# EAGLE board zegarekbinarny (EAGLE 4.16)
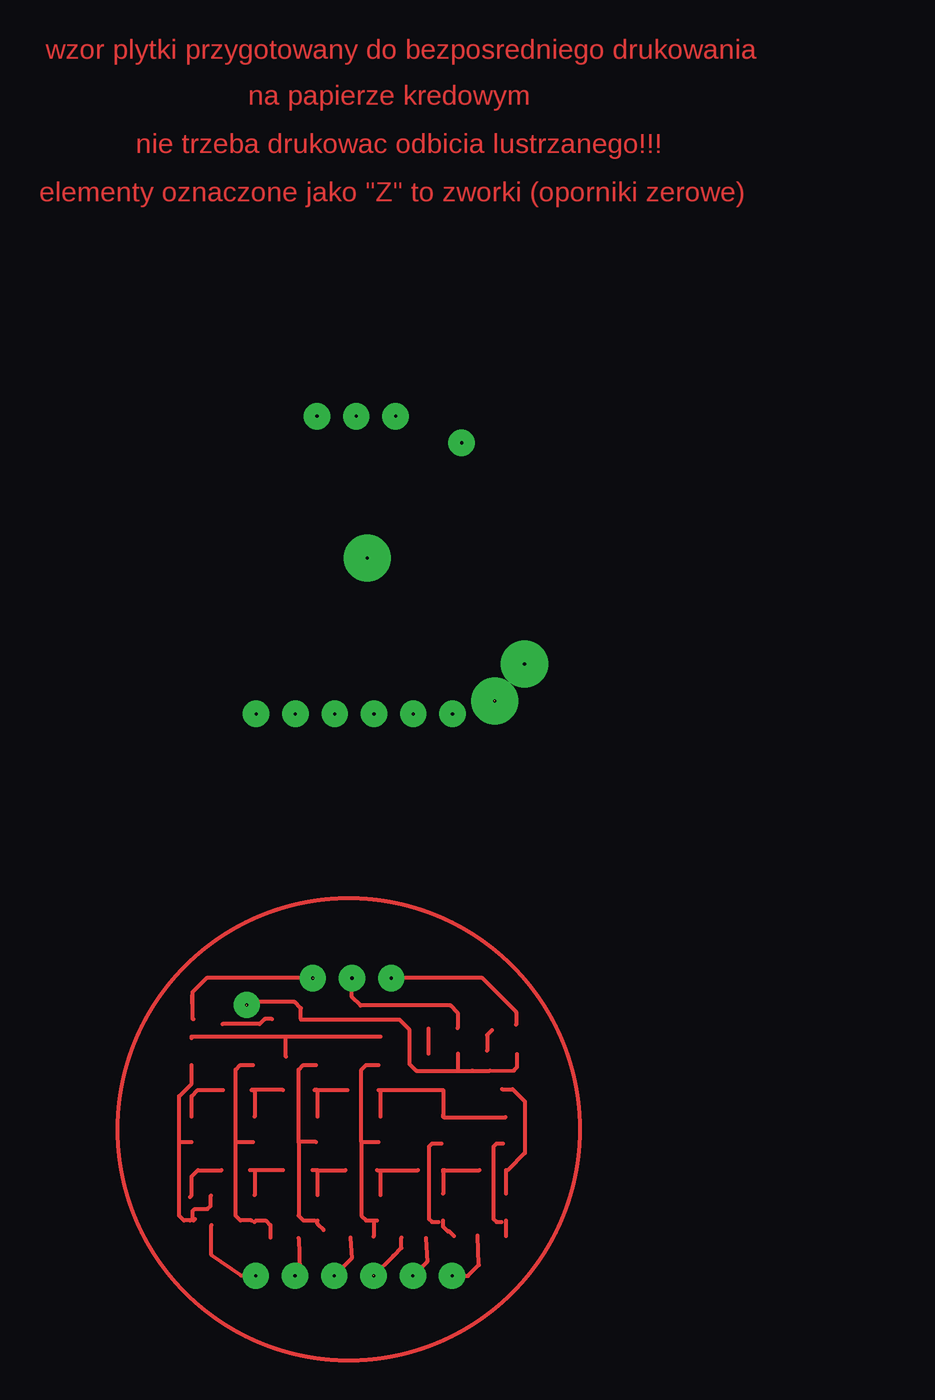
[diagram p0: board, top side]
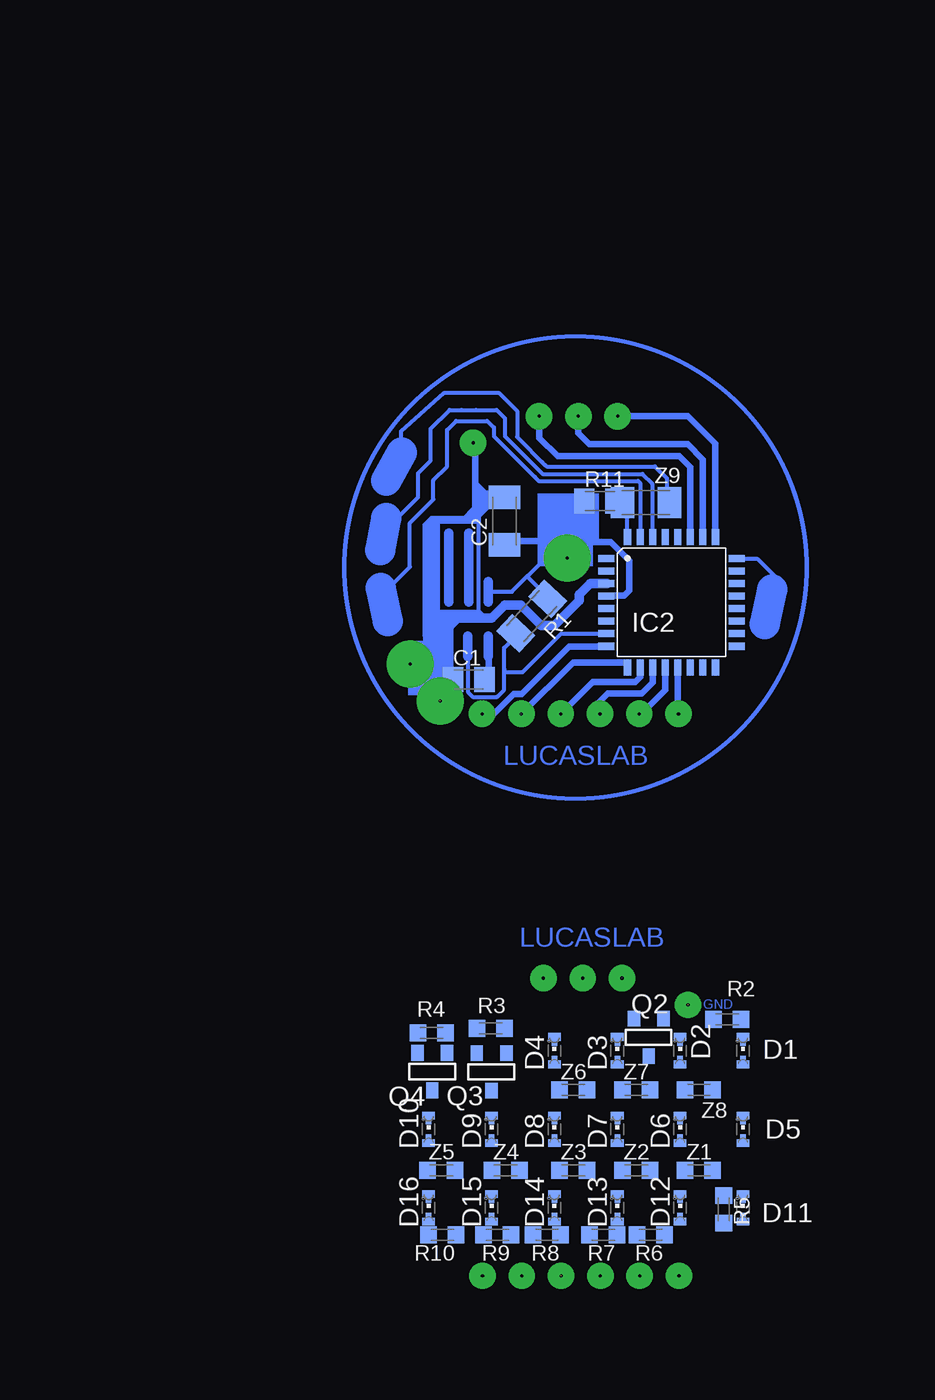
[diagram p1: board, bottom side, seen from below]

No outline drawn. Coordinates in mm, seen from the top.
Copper layers (1*16): Top 0.035mm / dielectric 1.5mm / Bottom 0.035mm
Design rules "default": minimum track width 10mil, minimum drill 24mil, track to track 8mil, track to pad 8mil, pad to pad 8mil, via to via 8mil, smd to smd 8mil, copper to edge 40mil, drill to drill 8mil, minimum pad ring 10mil, minimum via ring 8mil, stop-mask expansion 4mil, vias tented up to drill 0mil, thermal gap 10mil

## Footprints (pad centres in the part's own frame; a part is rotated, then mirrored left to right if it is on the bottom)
C0805K = smd 1.3 x 1.6: 1 -1,0; 2 1,0
C1206K = smd 1.5 x 2: 1 -1.5,0; 2 1.5,0
CHIPLED-0603-TTW = smd 0.8 x 0.5: A 0,-0.875; C 0,0.875 | smd 0.35 x 0.35: A@1 0,-0.5; C@1 0,0.5
VQFP32 = smd 1 x 0.45: 1 -4.15,2.8; 2 -4.15,2; 3 -4.15,1.2; 4 -4.15,0.4; 5 -4.15,-0.4; 6 -4.15,-1.2; 7 -4.15,-2; 8 -4.15,-2.8; 17 4.15,-2.8; 18 4.15,-2; 19 4.15,-1.2; 20 4.15,-0.4; 21 4.15,0.4; 22 4.15,1.2; 23 4.15,2; 24 4.15,2.8 | smd 0.45 x 1: 9 -2.8,-4.15; 10 -2,-4.15; 11 -1.2,-4.15; 12 -0.4,-4.15; 13 0.4,-4.15; 14 1.2,-4.15; 15 2,-4.15; 16 2.8,-4.15; 25 2.8,4.15; 26 2,4.15; 27 1.2,4.15; 28 0.4,4.15; 29 -0.4,4.15; 30 -1.2,4.15; 31 -2,4.15; 32 -2.8,4.15
SC-59 = smd 0.787 x 0.991: 1 -0.914,1.168; 2 0.965,1.168; 3 0.025,-1.219
C0603K = smd 1.05 x 1.08: 1 -0.875,0; 2 0.875,0

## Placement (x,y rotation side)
C1  [C0805K]  10.22,13.2 0 bottom
C2  [C1206K]  7.95,23.3 90 bottom
D1  [CHIPLED-0603-TTW]  -7.22,-10.43 0 bottom
D2  [CHIPLED-0603-TTW]  -3.23,-10.43 0 bottom
D3  [CHIPLED-0603-TTW]  0.78,-10.43 0 bottom
D4  [CHIPLED-0603-TTW]  4.78,-10.43 0 bottom
D5  [CHIPLED-0603-TTW]  -7.22,-15.43 0 bottom
D6  [CHIPLED-0603-TTW]  -3.23,-15.43 0 bottom
D7  [CHIPLED-0603-TTW]  0.78,-15.43 0 bottom
D8  [CHIPLED-0603-TTW]  4.78,-15.43 0 bottom
D9  [CHIPLED-0603-TTW]  8.78,-15.43 0 bottom
D10  [CHIPLED-0603-TTW]  12.78,-15.43 0 bottom
D11  [CHIPLED-0603-TTW]  -7.22,-20.43 0 bottom
D12  [CHIPLED-0603-TTW]  -3.23,-20.43 0 bottom
D13  [CHIPLED-0603-TTW]  0.78,-20.43 0 bottom
D14  [CHIPLED-0603-TTW]  4.78,-20.43 0 bottom
D15  [CHIPLED-0603-TTW]  8.78,-20.43 0 bottom
D16  [CHIPLED-0603-TTW]  12.78,-20.43 0 bottom
IC2  [VQFP32]  -2.67,18.12 0 bottom
Q2  [SC-59]  -1.2,-9.55 0 bottom
Q3  [SC-59]  8.8,-11.75 0 bottom
Q4  [SC-59]  12.57,-11.72 0 bottom
R1  [C1206K]  6.22,17.25 227 bottom
R2  [C0603K]  -6.22,-8.43 180 bottom
R3  [C0603K]  8.82,-9 180 bottom
R4  [C0603K]  12.57,-9.28 180 bottom
R5  [C0603K]  -6,-20.52 270 bottom
R6  [C0603K]  -1.35,-22.15 180 bottom
R7  [C0603K]  1.68,-22.15 180 bottom
R8  [C0603K]  5.25,-22.15 180 bottom
R9  [C0603K]  8.4,-22.15 180 bottom
R10  [C0603K]  11.9,-22.15 180 bottom
R11  [C0805K]  1.88,24.57 0 bottom
Z1  [C0603K]  -4.42,-18.02 0 bottom
Z2  [C0603K]  -0.42,-18.02 0 bottom
Z3  [C0603K]  3.58,-18.02 0 bottom
Z4  [C0603K]  7.88,-18.02 0 bottom
Z5  [C0603K]  11.97,-18.02 0 bottom
Z6  [C0603K]  3.58,-12.93 0 bottom
Z7  [C0603K]  -0.42,-12.93 0 bottom
Z8  [C0603K]  -4.42,-12.93 0 bottom
Z9  [C1206K]  -1.05,24.48 180 bottom

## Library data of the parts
C1 C2 R1 R11 Z9 = rcl
D1-D16 = led
IC2 = atmel
Q2-Q4 R2-R10 Z1-Z8 = ref-packages

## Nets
S$156: IC2.31

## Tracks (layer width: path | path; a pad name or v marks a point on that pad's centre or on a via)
S$44
  Top 0.254: -8.03,-16.23 -8.03,-13.32 -7.22,-12.53 -7.22,-11.32 | -8.03,-16.23 -8.03,-20.93 -7.72,-21.23 -7.33,-21.23 | -8.03,-16.23 -7.22,-16.23
S$56
  Top 0.254: -3.33,-11.32 -4.12,-11.32 -4.42,-11.62 -4.42,-16.23 | -4.42,-16.23 -4.42,-20.93 -4.12,-21.23 -3.42,-21.23 | -4.42,-16.23 -3.33,-16.23
S$57
  Top 0.254: 0.68,-11.32 -0.12,-11.32 -0.42,-11.62 -0.42,-16.23 | -0.42,-16.23 -0.42,-20.93 -0.12,-21.23 0.57,-21.23 | 0.68,-16.23 -0.42,-16.23
S$59
  Top 0.254: 4.67,-11.32 3.88,-11.32 3.58,-11.62 3.58,-16.23 | 3.58,-16.23 3.58,-20.93 3.88,-21.23 4.58,-21.23 | 3.58,-16.23 4.67,-16.23
S$69
  Top 0.254: 8.68,-16.32 8.07,-16.32 7.88,-16.52 7.88,-21.12 8.07,-21.32 8.47,-21.32
S$72
  Top 0.254: 12.57,-16.32 12.18,-16.32 11.97,-16.52 11.97,-21.12 12.18,-21.32 12.47,-21.32
S$94
  Top 0.254: -1.43,-12.93 -3.42,-12.93
S$95
  Top 0.254: 0.78,-12.93 2.67,-12.93 | 0.78,-12.93 0.57,-12.93 | 0.78,-12.93 0.78,-14.62
S$96
  Top 0.254: -3.23,-13.03 -3.23,-14.62
S$97
  Top 0.254: -5.22,-12.93 -6.83,-12.93 -7.22,-13.32 -7.22,-14.62
S$98
  Top 0.254: 4.78,-12.93 4.78,-14.62
S$99
  Top 0.254: 4.67,-12.93 8.78,-12.93 8.78,-14.53
S$100
  Top 0.254: -5.33,-18.02 -6.83,-18.02 -7.22,-18.43 -7.22,-19.62 -7.33,-19.73
S$101
  Top 0.254: -1.43,-18.02 -3.23,-18.02 | -3.23,-18.02 -3.52,-18.02 | -3.23,-18.02 -3.23,-19.62
S$102
  Top 0.254: 0.78,-18.02 2.58,-18.02 | 0.78,-18.02 0.47,-18.02 | 0.78,-18.02 0.78,-19.62
S$103
  Top 0.254: 4.58,-18.02 7.17,-18.02
S$104
  Top 0.254: 8.88,-18.02 11.07,-18.02 | 8.88,-18.02 8.78,-18.02 | 8.78,-19.52 8.78,-18.12 8.88,-18.02
S$105
  Top 0.254: 4.78,-18.23 4.78,-19.62
S$106  (via drill 0.2 pad 1.68)
  Top 0.254: -0.42,-22.35 -0.35,-24.45 v-0.65,-24.75
S$107  (via drill 0.2 pad 1.68)
  Top 0.254: 2.88,-22.32 2.95,-23.65 v1.85,-24.75
S$109  (via drill 0.2 pad 1.68)  (1 unrouted)
  Top 0.254: v4.35,-24.75 4.55,-24.55 | 4.35,-24.73 4.38,-24.73 5.6,-23.5 | 5.6,-23.5 5.62,-23.48 | 5.6,-23.5 6.12,-22.98 6.12,-22.32
S$110  (via drill 0.2 pad 1.68)
  Top 0.254: 7.67,-22.35 7.75,-23.85 v6.85,-24.75
S$111
  Top 0.254: 12.78,-21.23 12.78,-22.23
S$112
  Top 0.254: 8.78,-21.23 8.78,-21.62 9.07,-21.93 9.18,-21.93 9.47,-22.23
S$113
  Top 0.254: 0.78,-21.23 0.78,-21.43 1.18,-21.82
S$114
  Top 0.254: -2.23,-22.32 -2.23,-21.52 -2.52,-21.23 -3.12,-21.23 -3.23,-21.32
S$115
  Top 0.254: -7.03,-21.12 -7.12,-21.23
S$116
  Top 0.254: -7.22,-9.62 -7.22,-9.53 4.78,-9.53
S$117  (via drill 0.2 pad 1.68)
  Top 0.254: v9.35,-24.75 10.35,-24.75 11.05,-24.05 10.97,-22.2
S$119
  Top 0.254: 4.35,-21.27 4.35,-22.25
S$120
  Top 0.254: -7.17,-21.2 -7.17,-20.65 -7.03,-20.5 -6.22,-20.5 -6.03,-20.3 -6.03,-19.68 -6,-19.65
S$121  (via drill 0.2 pad 1.68)
  Top 0.254: v-3.15,-24.75 -3.17,-24.73 -4.08,-24.73 -5.97,-23.43 -5.97,-21.52
S$122
  Top 0.254: 12.78,-19.52 12.78,-18.02 12.88,-18.02 13.97,-16.93 13.97,-13.65 13.2,-12.88 12.53,-12.88
S$123
  Top 0.254: 13.28,-11.68 13.47,-11.47 13.47,-10.62
S$124
  Top 0.254: 11.88,-9.12 11.57,-9.43 11.57,-10.43
S$125
  Top 0.254: 7.85,-10.6 7.85,-9.03
S$126
  Top 0.254: 12.75,-14.65 8.8,-14.65 8.78,-14.62
S$127
  Top 0.254: -1.23,-10.8 -1.23,-9.55
S$128  (via drill 0.2 pad 1.68)  (1 unrouted)
  Top 0.254: -0.28,-8.4 -0.28,-7.72 -0.68,-7.33 -3.58,-7.33 -3.75,-7.5
  other vias: -3.73,-7.5
S$129
  Top 0.254: 13.25,-11.68 11.75,-11.7 10.6,-11.7 | 10.6,-11.7 10.65,-11.7 | 9.72,-11.7 10.6,-11.7 | 9.72,-11.7 9.72,-10.6 | -0.28,-8.45 6,-8.45 6.65,-9.1 6.65,-11.28 7.08,-11.7 9.72,-11.7
S$130
  Top 0.254: -2.12,-8.4 -2.58,-8.4 -2.9,-8.72 -5.25,-8.72
S$132  (via drill 0.2 pad 1.68)  (1 unrouted)
  Top 0.254: 0.5,-5.8 -6.28,-5.8 -7.17,-6.7 -7.17,-7.45 | -7.17,-7.45 -7.17,-8.38 -7.12,-8.43 | -7.17,-7.45 -7.17,-6.88
  other vias: 0.47,-5.8
S$134  (via drill 0.2 pad 1.68)
  Top 0.254: 9.7,-8.97 9.7,-8 9.25,-7.55 3.52,-7.55 2.98,-7 v2.98,-5.8
S$135  (via drill 0.2 pad 1.68)
  Top 0.254: v5.47,-5.8 11.28,-5.8 13.43,-7.95 13.43,-8.78
S$136
  Bottom 0.61: 11.51,15.98 11.51,14.69
S$137
  Bottom 0.61: 8.97,18.14 8.97,19.45
S$138
  Bottom 0.61: 11.51,18.14 11.51,22.55
S$139
  Bottom 0.61: 10.23,18.14 10.23,22.55
S$140
  Bottom 0.254: 12.18,17.52 9.57,17.52 9.57,23.27 12.18,23.27 12.18,17.52
S$141
  Bottom 0.61: 1.4,19.32 2.5,19.32 3.2,18.62 3.2,18.23 4.78,16.65 5.62,16.65 6.92,17.95 7.92,17.95 8.75,17.12 10.93,17.12 | 10.93,17.12 11.35,17.12 | 11.5,15.88 11.5,16.65 | 11.5,16.65 11.5,17.3 | 11.5,16.65 11.4,16.65 10.93,17.12
S$142
  Bottom 0.61: 11.4,16.93 11.78,17.3 11.53,17.3 11.4,17.18
S$143
  Bottom 0.61: 11.28,17.27 12.72,17.27 12.72,16.57 11.93,15.78 11.93,16.52 12.3,16.9
S$144
  Bottom 0.61: 11.35,16.93 11.8,16.93 11.85,16.98
S$145
  Bottom 0.61: 12.85,16.02 12.82,16.02 12.75,15.95 12.75,15.93 11.5,14.68 11.5,15.68 | 11.5,15.68 11.5,16.65 11.53,16.68 11.53,16.65 | 11.5,15.68 11.53,15.65 | 11.5,12.18 11.5,15.68
S$146
  Bottom 0.254: 9.6,17.57 9.3,17.27
S$147
  Bottom 0.61: 8.97,14.69 8.97,15.98
S$148
  Bottom 1.93: 15.47,25.88 14.5,27.65
S$149
  Bottom 1.93: 15.88,21.45 15.47,23.48
S$150  (via drill 0.2 pad 3)
  Bottom 0.254: 1.5,18.52 0.35,18.52 0,18.88 | v3.95,20.95 5.33,20.95 7.47,18.8 8.95,18.8
  Bottom 0.406: 1.07,18.55 0.33,18.55 0,18.88 0,20.77 1.18,21.95 2.95,21.95 v3.95,20.95 5.03,22.02 7.2,22.02
S$151
  Bottom 0.406: 9.65,23.4 9.65,23.48 9.82,23.65 9.82,23.93 | 9.82,23.93 9.82,25.77 | 9.82,25.77 9.82,27.75 | 9.82,23.93 9.82,23.7 10.1,23.43 12.12,23.43 12.25,23.3 12.25,22.75 12.43,22.75 | 9.82,25.77 9.82,25.7 9.28,25.15
  Bottom 0.61: 12.43,22.95 12.43,22.75 12.43,17.07
S$152
  Bottom 0.406: 12.8,16.02 12.95,16.02 12.95,23.05 12.57,23.43 11.97,23.43
S$153
  Bottom 0.406: 12.8,23.07 12.8,20.48 12.72,20.4
S$154
  Bottom 0.406: 12.75,20.35 12.75,17.32 12.57,17.15
S$155
  Bottom 0.254: 14.53,28.23 14.53,29.02 11.78,31.48 10.57,31.48 | -2.38,24.88 -2.38,26.02 -1.62,26.77 5.28,26.77 5.38,26.88 | 10.57,31.48 10.12,31.48 | 5.38,26.88 5.58,27.07 | 10.57,31.48 8.32,31.48 7.15,30.3 7.15,28.65 5.38,26.88
S$156
  Bottom 0.254: 11.6,28.12 11.6,26.77 12.47,25.9 12.47,24.68 13.97,23.18 13.97,20.38 15.45,18.9 16.05,18.9 | 11.6,28.12 11.6,28.48 | IC2.31 -0.68,25.73 -0.55,25.85 5.78,25.85 5.9,25.98 | 5.9,25.98 6.03,26.1 | 11.6,28.12 11.6,29.1 11.03,29.68 9.05,29.68 8.62,29.25 8.62,28.7 5.9,25.98
S$157
  Bottom 0.406: 9.8,25.05 7.25,25.05
S$158
  Bottom 0.406: 9.72,23.4 9.72,23.55 8.82,24.45 7.95,24.45 7.92,24.48
S$159
  Bottom 0.406: 8.07,24.77 8.93,24.77 9.65,24.05 9.65,24.5 9.3,24.85 9.45,24.85 9.53,24.77
S$160
  Bottom 0.406: 10.72,23.4 10.53,23.4 9.88,24.05
S$161
  Bottom 1.93: -8.62,16.75 -9.07,18.93
S$162
  Bottom 1.93: 15.38,16.93 15.82,19.02
S$163
  Bottom 0.254: -6.7,20.88 -8.18,20.88 -9.62,19.43
S$164
  Bottom 0.254: 5.65,18.88 5.65,18.9 6.47,19.73
S$165  (via drill 0.2 pad 3)  (1 unrouted)
  Bottom 0.61: 12.35,12.7 12.35,12.72 12.38,12.75 12.38,13.03 12.35,13.05 12.35,15.1 12.05,14.8 12.05,11.88 12.85,12.68 12.85,16.12 | 11.55,15.2 11.93,15.2 12.85,16.12 | 12.85,16.12 12.85,16.4
  other vias: 12.05,11.85
S$166  (via drill 0.2 pad 3)
  other vias: 13.95,14.2
S$167
  Bottom 0.254: 0.12,22.15 0.12,24.27 0.15,24.3
S$168
  Bottom 0.61: 10.28,14.66 10.28,15.96
S$169
  Bottom 0.254: 10.25,14.78 10.25,12.38 9.97,12.1 8.43,12.1 7.97,12.55 7.97,13.9 | 1.25,16.12 4.35,16.12 6.8,13.68 7.97,13.68 7.97,13.9 | 7.35,15.93 7.35,15.85 7.97,15.22 7.97,13.9
S$170  (via drill 0.2 pad 1.68)  (1 unrouted)
  Bottom 0.406: 0.12,14.3 3.58,14.3 6.88,11 6.9,10.97
  other vias: 6.88,11.03
S$171  (via drill 0.2 pad 1.68)
  Bottom 0.406: -3.08,13.8 -3.08,11.07 v-3.12,11.03
S$172  (via drill 0.2 pad 1.68)
  Bottom 0.406: -3.38,29.98 v0.75,29.98 | -3.38,29.98 -3.7,29.98 | -5.47,22.32 -5.47,28.23 -3.73,29.98 -3.38,29.98
S$173  (via drill 0.2 pad 1.68)
  Bottom 0.254: v9.38,11.03 9.4,11.05
  Bottom 0.406: v9.38,11.03 8.65,11.03 7.38,12.3 6.85,12.3 3.83,15.32 1.82,15.32
S$174  (via drill 0.2 pad 1.68)
  other vias: 9.95,28.27
S$175  (via drill 0.2 pad 1.68)
  Bottom 0.406: v3.25,29.98 3.25,28.9 2.55,28.2 -3.7,28.2 -4.67,27.23 -4.67,22.52
S$176
  Bottom 0.254: -1.45,22.32 -1.45,25.68 -0.82,26.3 5.53,26.3 5.58,26.35 | 5.58,26.35 5.8,26.57 | 10.68,30.38 11.45,30.38 12.65,29.18 12.65,27.15 13.45,26.35 13.45,24.82 14.62,23.65 15.97,23.65 | 10.68,30.38 9.75,30.38 | 10.68,30.38 8.45,30.38 7.92,29.85 7.92,28.7 5.58,26.35
S$177
  Bottom 0.406: -3.88,22.23 -3.88,26.73 -3.17,27.43 4.58,27.43 5.72,28.57 5.72,29.98
S$178  (via drill 0.2 pad 1.68)
  other vias: 5.75,29.98
S$179  (via drill 0.2 pad 1.68)
  Bottom 0.406: -0.7,13.62 -0.7,13.38 -0.38,13.05 2.35,13.05 v4.38,11.03
S$180  (via drill 0.2 pad 1.68)
  Bottom 0.406: -1.48,13.82 -1.48,13.03 -0.78,12.32 1.38,12.32 1.88,11.82 v1.88,11.03
S$181  (via drill 0.2 pad 1.68)
  Bottom 0.406: -2.27,13.53 -2.27,12.55 -0.75,11.03 v-0.62,11.03
S$182
  Bottom 0.406: 8.95,14.97 8.95,13.1 8.93,13.07
(copper drawn outside any net)
  shapes: Bottom area x4, Bottom circle x2, Top circle x1

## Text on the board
Top: wzor plytki przygotowany do bezposredniego drukowania | na papierze kredowym | nie trzeba drukowac odbicia lustrzanego!!! | elementy oznaczone jako "Z" to zworki (oporniki zerowe)
Bottom: LUCASLAB | LUCASLAB | GND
